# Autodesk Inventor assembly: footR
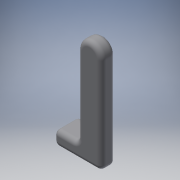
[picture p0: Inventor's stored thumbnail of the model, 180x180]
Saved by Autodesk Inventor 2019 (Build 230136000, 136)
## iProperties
Created: 2020-09
Part Number: footR
Material: 一般
Document SubType Name: Assembly
Designer: kikut
Author: kikut
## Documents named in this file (2)
- F:\openFOAM\basilisk\oversetmeshfootR\footR.iam
- F:\openFOAM\basilisk\oversetmeshfootR\footR.ipt
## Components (1 placed, 1 different names)
1. footR:1 — メイト:1, メイト:2
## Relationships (2: Mate 2)
- メイト:1 [Mate]: footR:1
- メイト:2 [Mate]: footR:1
